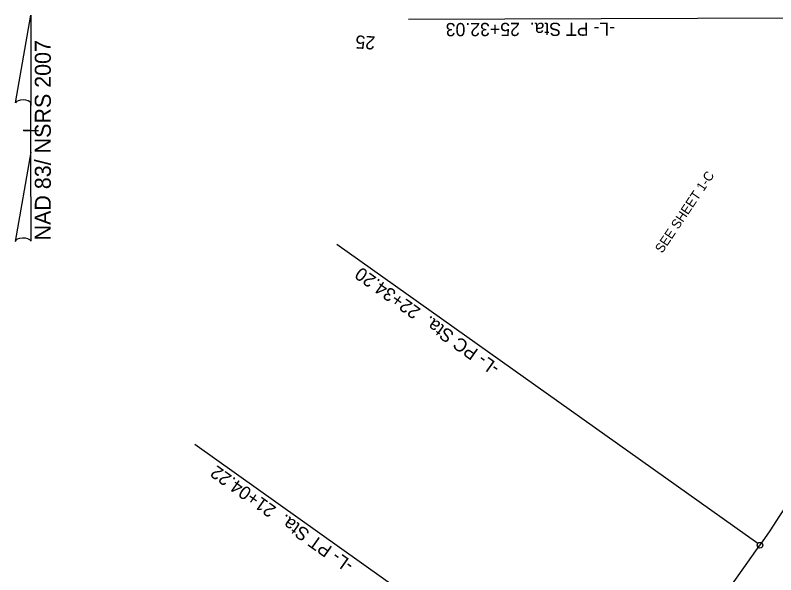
# Model space of a CAD drawing. Extents: x 1716813 to 1718091, y 800228 to 801730.
# Drawn here: x 1717425.4 to 1717828.4, y 801433.3 to 801729.7 of the extents above; entities that cross this region are included whole.
import ezdxf

# ---------------------------------------------------------------- set-up
doc = ezdxf.new("R2010")
doc.units = 0
for name, color, linetype in [('Prop DSN Text', 7, 'Continuous'), ('Prop Horizontal Alignment', 7, 'Continuous'), ('Prop Horizontal Alignment Station Label', 7, 'Continuous'), ('Prop Horizontal Alignment Tick Label', 7, 'Continuous'), ('Prop North Arrow NAD83 for Plan Sheets CELL', 7, 'Continuous')]:
    doc.layers.add(name, color=color, linetype=linetype)

msp = doc.modelspace()

# ---------------------------------------------------------------- linework, layer by layer
at = {"layer": 'Prop Horizontal Alignment'}
msp.add_line((1717744.81, 801342.98), (1717820.08, 801448.95), dxfattribs=at)
msp.add_arc((1717428.77, 801726.93), 480, 324.6117, 0.1626, dxfattribs=at)
at = {"layer": 'Prop Horizontal Alignment Station Label'}
for p, q in [((1717907.26, 801728.29), (1717633.77, 801727.51)), ((1717818.86, 801449.82), (1717595.89, 801608.21)), ((1717743.58, 801343.85), (1717520.61, 801502.24))]:
    msp.add_line(p, q, dxfattribs=at)
msp.add_circle((1717820.08, 801448.95), 1.5, dxfattribs=at)
at = {"layer": 'Prop North Arrow NAD83 for Plan Sheets CELL'}
for p, q in [((1717425.47, 801683.34), (1717433.67, 801729.69)), ((1717433.72, 801729.69), (1717433.67, 801729.69)), ((1717433.72, 801729.69), (1717433.67, 801729.69)), ((1717433.72, 801729.69), (1717433.72, 801681.89)), ((1717433.72, 801657.09), (1717433.72, 801683.29)), ((1717433.72, 801681.89), (1717433.72, 801683.24)), ((1717429.72, 801668.69), (1717429.67, 801668.69)), ((1717433.27, 801668.69), (1717429.72, 801668.69)), ((1717429.77, 801668.69), (1717437.77, 801668.69)), ((1717433.72, 801657.09), (1717425.37, 801609.84)), ((1717433.77, 801610.04), (1717433.72, 801657.09))]:
    msp.add_line(p, q, dxfattribs=at)
for centre, start_param, end_param in [((1717429.6, 801682.85), 0.216388, 2.908219), ((1717429.6, 801609.68), 0.201328, 3.141593)]:
    msp.add_ellipse(centre, major_axis=(4.23, -0.03), ratio=0.461098, start_param=start_param, end_param=end_param, dxfattribs=at)

# ---------------------------------------------------------------- texts
at = {"layer": 'Prop DSN Text'}
msp.add_text('SEE SHEET 1-C', height=5, rotation=56.2051, dxfattribs=at).set_placement((1717768.22, 801603.29))
at = {"layer": 'Prop Horizontal Alignment Station Label'}
for s, rotation, p in [('-L- PT Sta.  25+32.03', 180.1626, (1717743.27, 801725.82)), ('-L- PC Sta.  22+34.20', 144.6117, (1717682.7, 801544.09)), ('-L- PT Sta.  21+04.22', 144.6117, (1717605.31, 801439.62))]:
    msp.add_text(s, height=7, rotation=rotation, dxfattribs=at).set_placement(p)
at = {"layer": 'Prop Horizontal Alignment Tick Label'}
msp.add_text('25', height=7, rotation=176.3389, dxfattribs=at).set_placement((1717616.31, 801718.44))
at = {"layer": 'Prop North Arrow NAD83 for Plan Sheets CELL'}
msp.add_text('NAD 83/ NSRS 2007', height=8.5, rotation=90, dxfattribs=at).set_placement((1717444.24, 801610.39))

doc.saveas('drawing.dxf')
